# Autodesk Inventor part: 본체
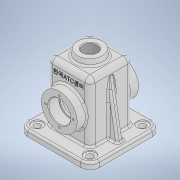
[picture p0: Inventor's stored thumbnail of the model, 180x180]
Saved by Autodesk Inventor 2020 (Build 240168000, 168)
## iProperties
Created: 2021-07
Part Number: 본체
Material: 일반
Document SubType Name: Modeling
Designer: Owner
Density: 1 g/cm^3
Appearance: 기본값
Mass: 278.271 g
Surface Area: 858.464 cm^2
Volume: 278.271 cm^3
Author: Owner
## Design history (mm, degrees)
sketch "스케치1"
  geometry: L1 (34, 34)-(-34, 34); L2 (-34, 34)-(-34, -34); L3 (-34, -34)-(34, -34); L4 (34, -34)-(34, 34); L5 (34, 34)-(-34, -34); L6 (-34, 34)-(34, -34); 1 further point
  constraints: 12 end point, 2 midpoint, 2 parallel, 1 horizontal, 1 perpendicular
  dimensions: "d0" = 68 distance of L3.end L2.end; "d1" = 68 distance of L2.end L1.end
extrude "돌출1" new body sketch "스케치1" stored distance "d2" = 105; taper "d3" = 0 deg
fillet "모깎기1" dims "d4" = 8
feature "쉘1" dims "d5" = 5
node "작업 평면1"
sketch "스케치2"
  geometry: C1 r 20 at (0, 0); 1 further point
  constraints: 1 centre point, 1 coincident
  dimensions: "d7" = 40 diameter of C1
extrude "돌출2" join sketch "스케치2" stored distance "d8" = 105; taper "d9" = 8 deg
sketch "스케치3"
  geometry: L1 (57, 57)-(-57, 57); L2 (-57, 57)-(-57, -57); L3 (-57, -57)-(57, -57); L4 (57, -57)-(57, 57); L5 (57, 57)-(-57, -57); L6 (-57, 57)-(57, -57); L7 (-26, -34)-(26, -34) reference; L8 (34, -26)-(34, 26) reference; L9 (26, 34)-(-26, 34) reference; L10 (-34, 26)-(-34, -26) reference; A1 r 8 centre (26, -26) between (26, -34) and (34, -26) reference; A2 r 8 centre (26, 26) between (34, 26) and (26, 34) reference; A3 r 8 centre (-26, 26) between (-26, 34) and (-34, 26) reference; A4 r 8 centre (-26, -26) between (-34, -26) and (-26, -34) reference; 1 further point
  constraints: 12 end point, 2 midpoint, 2 parallel, 1 horizontal, 1 perpendicular
  dimensions: "d10" = 114 distance of L3.end L2.end; "d11" = 114 distance of L2.end L1.end
extrude "돌출3" join sketch "스케치3" distance "d12" = 10; taper "d13" = 0 deg
fillet "모깎기2" dims "d14" = 15
node "작업 평면2"
sketch "스케치4"
  geometry: L1 (68, -97)-(-16, -97) reference; L2 (46, 18)-(6, 18) reference; C1 r 28.5 at (26, -45); 2 further points
  constraints: 1 centre point, 1 coincident, 1 midpoint, 1 vertical alignment
  dimensions: "d16" = 57 diameter of C1; "d76" = 52 distance from line of L1 point (26, -45)
extrude "돌출4" join sketch "스케치4" stored distance "d17" = 10; taper "d18" = 0 deg
sketch "스케치5"
  geometry: C1 r 28.5 at (0, 0) reference; 2 further points
  constraints: 1 coincident
hole "구멍1" sketch "스케치5" at (0, 0) diameter "d19" = 30; stored, may be unused: countersink angle "d23" = 90 deg, drill point angle "d25" = 0 deg; dims "d20" = 6, "d21" = 35, "d22" = 17, "d24" = 20
chamfer "모따기1" distance "d26" = 1; stored, may be unused: second distance "d27" = 2, angle "d28" = 45 deg
fillet "모깎기3" dims "d29" = 0.3
sketch "스케치7"
  geometry: C1 r 20 at (0, 0) reference; 2 further points
  constraints: 1 coincident
hole "구멍2" sketch "스케치7" at (0, 0) diameter "d30" = 22.83494; stored, may be unused: countersink angle "d34" = 90 deg, drill point angle "d36" = 0 deg; dims "d31" = 50, "d32" = 35, "d33" = 17, "d35" = 59.3
sketch "스케치8" dims "d37" = 44
  geometry: C1 r 28.5 at (0, 0) reference; 3 further points
  constraints: 2 vertical alignment, 1 coincident, 2 other
hole "구멍3" sketch "스케치8" at (0, 22) diameter "d38" = 3.242; stored, may be unused: countersink angle "d42" = 90 deg, drill point angle "d44" = 118 deg; dims "d39" = 8, "d40" = 35, "d41" = 17, "d43" = 10
sketch "스케치9"
  geometry: A1 r 15 centre (-42, 42) between (-42, 57) and (-57, 42) reference; A2 r 15 centre (-42, -42) between (-57, -42) and (-42, -57) reference; A3 r 15 centre (42, 42) between (57, 42) and (42, 57) reference; A4 r 15 centre (42, -42) between (42, -57) and (57, -42) reference; 5 further points
  constraints: 4 coincident
hole "구멍4" sketch "스케치9" at (-42, 42), (-42, -42), (42, 42), (42, -42) diameter "d48" = 10; stored, may be unused: countersink angle "d52" = 90 deg, drill point angle "d54" = 0 deg; dims "d49" = 8, "d50" = 18, "d51" = 2, "d53" = 10
sketch "스케치10"
  geometry: L1 (-39.358, 12.182)-(-49, -42.5); L2 (-57, -42.5)-(-42, -42.5) reference; L3 (-57, -42.5)-(-57, -52.5) reference; L4 (-42, -42.5)-(42, -42.5) reference; 2 further points
  constraints: 2 end point, 1 point on line
  dimensions: "d55" = 8 distance from line of L3 L1.end; "d56" = 10 deg angle of L3 L1
feature "리브1" sketch "스케치10" dims "d57" = 1, "d58" = 10, "d59" = 0, "d60" = 0, "d61" = 1, "d62" = 1
fillet "모깎기4" dims "d63" = 3
fillet "모깎기5" dims "d64" = 3
fillet "모깎기6" dims "d65" = 3
fillet "모깎기7" dims "d66" = 3
fillet "모깎기8" dims "d67" = 3
fillet "모깎기9" dims "d68" = 3
chamfer "모따기2" distance "d69" = 1; stored, may be unused: second distance "d70" = 2, angle "d71" = 45 deg
node "작업 평면3"
sketch "스케치11"
  geometry: L1 (46, 18)-(6, 18) reference; 2 further points
  constraints: 1 vertical alignment, 1 other
  dimensions: "d73" = 25 distance from line of L1 point (26, -7)
feature "엠보싱1" sketch "스케치11" dims "d0" = 68, "d1" = 68, "d74" = 0.5, "d75" = 0
node "솔리드1"
mirror "미러1"
pattern_circular "원형 패턴1" dims angle "d46" = 360 deg
mirror "미러2"
mirror "미러3"
feature "A9D066F2-1C7D-4E18-AEED-F7BC21143FA4" dims "d19" = 30, "d20" = 6, "d21" = 35, "d22" = 17, "d23" = 90 deg, "d24" = 20, "d25" = 0
other parameters: "d6" = -115, "d15" = 15, "d72" = 0.5
